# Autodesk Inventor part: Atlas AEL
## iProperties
Author: John A. Hunter
Shininess: 64.0
Angle Display Precision: 2
Document Length Units: 11272
Document Angle Units: 11286
Document Time Units: 11279
Document Mass Units: 11290
Document Length Units Precision: 3
Document Angle Units Precision: 2
Compacted: True
PropertySet Name: _Private Model Information
Created: 2002-09
Part Number: Atlas AEL
Material: Steel, Mild
Catalog Web Link: www.atlas-eng.com
Description: AELS-632-80
Vendor: Atlas Engineering
Document SubType Name: Modeling
Designer: John A. Hunter
Control State: 0
Master: False
Checked Out: False
PropertySet Name: Design Tracking Control
Density: 0.0
Volumn: 0.0
Area: 0.0
PropertySet Name: Model Information
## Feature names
1. Extrusion1
2. Extrusion2
3. Chamfer1
4. Hole1
